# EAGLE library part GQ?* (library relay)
ULTRA-SMALL PACKAGE FLAT POLARIZED RELAY NAiS Source: http://www.mew-europe.com/.. en_ds_61008_0000.pdf
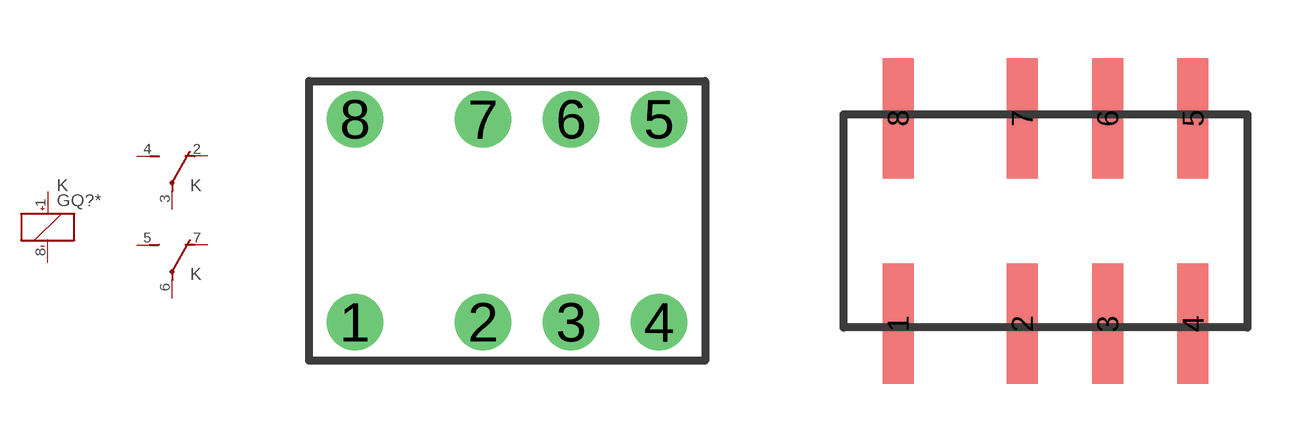
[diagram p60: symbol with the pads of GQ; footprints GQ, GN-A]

Designator prefix K; gates 1=K+- 2=U 3=U

## GQ2001H (OC_FARNELL: unknown; OC_NEWARK: unknown), GQ20003 (MPN: AGQ20003; OC_FARNELL: unknown; OC_NEWARK: 13P0847), GQ2004H (MPN: AGQ2004H; OC_FARNELL: 3104813; OC_NEWARK: 13P0851), GQ20006 (MF: AROMAT/ MATSUSHITA; MPN: AGQ20006; OC_FARNELL: unknown; OC_NEWARK: 10C3360), GQ20009 (MF: AROMAT/ MATSUSHITA; MPN: AGQ20009; OC_FARNELL: unknown; OC_NEWARK: 10C3361), GQ20012 (MPN: AGQ20012; OC_FARNELL: 3104825; OC_NEWARK: 13P0849), GQ20024 (MPN: AGQ20024; OC_FARNELL: unknown; OC_NEWARK: 13P0850)  [GQ]
1  1:+  pas
2  2:O  pas
3  2:P  pas
4  2:S  pas
5  3:S  pas
6  3:P  pas
7  3:O  pas
8  1:-  pas

## GQ200A1H (OC_FARNELL: unknown; OC_NEWARK: unknown), GQ200A03 (MPN: AGQ200A03; OC_FARNELL: 1448336; OC_NEWARK: 13P0835), GQ200A4H (MPN: AGQ200A4H; OC_FARNELL: 3104837; OC_NEWARK: 13P0838), GQ200A06 (OC_FARNELL: unknown; OC_NEWARK: unknown), GQ200A09 (MF: AROMAT/ MATSUSHITA; MPN: AGQ200A09Z; OC_FARNELL: unknown; OC_NEWARK: 10C3339), GQ200A12 (MPN: AGQ200A12; OC_FARNELL: 3104849; OC_NEWARK: 13P0836), GQ200A24 (MPN: AGQ200A24; OC_FARNELL: 1448337; OC_NEWARK: 13P0837)  [GN-A]
Pads as for GQ

## GQ200S1H (MPN: AGQ200S1H; OC_FARNELL: unknown; OC_NEWARK: 13P0842), GQ200S03 (MF: AROMAT/ MATSUSHITA; MPN: AGQ200S03; OC_FARNELL: unknown; OC_NEWARK: 10C3345), GQ200S4H (MF: AROMAT/ MATSUSHITA; MPN: AGQ200S4H; OC_FARNELL: unknown; OC_NEWARK: 10C3357), GQ200S06 (OC_FARNELL: unknown; OC_NEWARK: unknown), GQ200S09 (OC_FARNELL: unknown; OC_NEWARK: unknown), GQ200S12 (MF: AROMAT/ MATSUSHITA; MPN: AGQ200S12; OC_FARNELL: unknown; OC_NEWARK: 10C3353), GQ200S24 (MF: AROMAT/ MATSUSHITA; MPN: AGQ200S24; OC_FARNELL: unknown; OC_NEWARK: 10C3355)  [GN-S]
Pads as for GQ

## GQ2101H (MF: AROMAT/ MATSUSHITA; MPN: AGQ2101H; OC_FARNELL: unknown; OC_NEWARK: 10C3394), GQ21003 (MF: AROMAT/ MATSUSHITA; MPN: AGQ21003; OC_FARNELL: unknown; OC_NEWARK: 10C3391), GQ2104H (MPN: AGQ2104H; OC_FARNELL: unknown; OC_NEWARK: 15P8587), GQ21006 (OC_FARNELL: unknown; OC_NEWARK: unknown), GQ21009 (MPN: AGQ21009; OC_FARNELL: unknown; OC_NEWARK: 15P8586), GQ21012 (OC_FARNELL: unknown; OC_NEWARK: unknown), GQ21024 (MF: AROMAT/ MATSUSHITA; MPN: AGQ21024; OC_FARNELL: unknown; OC_NEWARK: 10C3396)  [GQ]
1  1:-  pas
2  2:O  pas
3  2:P  pas
4  2:S  pas
5  3:S  pas
6  3:P  pas
7  3:O  pas
8  1:+  pas

## GQ210A1H (MPN: AGQ210A1H; OC_FARNELL: unknown; OC_NEWARK: 15P8581), GQ210A03 (MPN: AGQ210A03; OC_FARNELL: unknown; OC_NEWARK: 15P8580), GQ210A4H (MPN: AGQ210A4H; OC_FARNELL: unknown; OC_NEWARK: 15P8582), GQ210A06 (OC_FARNELL: unknown; OC_NEWARK: unknown), GQ210A09 (OC_FARNELL: unknown; OC_NEWARK: unknown), GQ210A12 (OC_FARNELL: unknown; OC_NEWARK: unknown), GQ210A24 (OC_FARNELL: unknown; OC_NEWARK: unknown)  [GQ-A]
Pads as for GQ

## GQ210S1H (OC_FARNELL: unknown; OC_NEWARK: unknown), GQ210S03 (OC_FARNELL: unknown; OC_NEWARK: unknown), GQ210S4H (MPN: AGQ210S4H; OC_FARNELL: unknown; OC_NEWARK: 15P8583), GQ210S06 (OC_FARNELL: unknown; OC_NEWARK: unknown), GQ210S09 (OC_FARNELL: unknown; OC_NEWARK: unknown), GQ210S12V (OC_FARNELL: unknown; OC_NEWARK: unknown), GQ210S24 (OC_FARNELL: unknown; OC_NEWARK: unknown)  [GN-S]
Pads as for GQ

## Footprint GQ (pad centres in mm)
ULTRA-SMALL PACKAGE FLAT POLARIZED RELAY NAiS Source: http://www.mew-europe.com/.. en_ds_61008_0000.pdf
drill 0.9 round: 1 -3.8,-2.54; 2 -0.6,-2.54; 3 1.6,-2.54; 4 3.8,-2.54; 5 3.8,2.54; 6 1.6,2.54; 7 -0.6,2.54; 8 -3.8,2.54

## Footprint GN-A (pad centres in mm)
ULTRA-SMALL PACKAGE SLIM POLARIZED RELAY NAiS Source: http://www.mew-europe.com/.. en_ds_61007_0000.pdf
smd 0.8 x 3.1: 1 -3.835,-2.65; 2 -0.635,-2.65; 3 1.565,-2.65; 4 3.765,-2.65; 5 3.765,2.65; 6 1.565,2.65; 7 -0.635,2.65; 8 -3.835,2.65

## Footprint GN-S (pad centres in mm)
ULTRA-SMALL PACKAGE SLIM POLARIZED RELAY NAiS Source: http://www.mew-europe.com/.. en_ds_61007_0000.pdf
smd 0.8 x 2.25: 1 -3.835,-2.225; 2 -0.635,-2.225; 3 1.565,-2.225; 4 3.765,-2.225; 5 3.765,2.225; 6 1.565,2.225; 7 -0.635,2.225; 8 -3.835,2.225

## Footprint GQ-A (pad centres in mm)
ULTRA-SMALL PACKAGE FLAT POLARIZED RELAY NAiS Source: http://www.mew-europe.com/.. en_ds_61008_0000.pdf
smd 0.8 x 2.66: 1 -3.8,-3.37; 2 -0.6,-3.37; 3 1.6,-3.37; 4 3.8,-3.37; 5 3.8,3.37; 6 1.6,3.37; 7 -0.6,3.37; 8 -3.8,3.37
